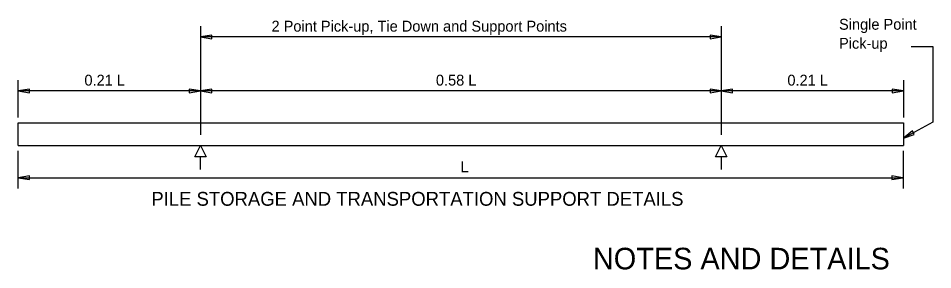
# Model space of a CAD drawing. Extents: x 0.4 to 30.4, y 0.1 to 19.4.
# Drawn here: x 17.73 to 30.43, y 0.15 to 3.64 of the extents above; entities that cross this region are included whole.
import ezdxf

# ---------------------------------------------------------------- set-up
doc = ezdxf.new("R2010")
doc.units = 0
for name, color, linetype in [('Dimension', 7, 'Continuous'), ('SheetPileConc', 7, 'Continuous'), ('TextStructures', 7, 'Continuous')]:
    doc.layers.add(name, color=color, linetype=linetype)

msp = doc.modelspace()

# ---------------------------------------------------------------- linework, layer by layer
at = {"layer": 'Dimension'}
for p, q in [((20.259, 3.529), (20.259, 2.02)), ((27.492, 3.529), (27.492, 2.02)), ((27.492, 3.381), (20.259, 3.381)), ((17.729, 2.26), (17.729, 2.779)), ((30.022, 2.779), (30.022, 2.26)), ((20.259, 2.631), (17.729, 2.631)), ((27.492, 2.631), (20.259, 2.631)), ((30.022, 2.631), (27.492, 2.631)), ((17.729, 1.277), (17.729, 1.797)), ((30.022, 1.277), (30.022, 1.797)), ((20.26, 1.541), (20.26, 1.715)), ((27.493, 1.541), (27.493, 1.715)), ((17.729, 1.426), (30.022, 1.426))]:
    msp.add_line(p, q, dxfattribs=at)
for points in [[(20.259, 3.381), (20.415, 3.355), (20.415, 3.407)], [(27.492, 3.381), (27.336, 3.407), (27.336, 3.355)], [(17.729, 2.631), (17.886, 2.605), (17.886, 2.657)], [(20.259, 2.631), (20.103, 2.657), (20.103, 2.605)], [(20.259, 2.631), (20.415, 2.605), (20.415, 2.657)], [(27.492, 2.631), (27.336, 2.657), (27.336, 2.605)], [(27.492, 2.631), (27.648, 2.605), (27.648, 2.657)], [(30.022, 2.631), (29.865, 2.657), (29.865, 2.605)], [(30.023, 1.977), (30.172, 2.028), (30.147, 2.075)], [(20.259, 1.871), (20.338, 1.715), (20.18, 1.715)], [(27.492, 1.871), (27.571, 1.715), (27.413, 1.715)], [(17.729, 1.426), (17.886, 1.399), (17.886, 1.452)], [(30.015, 1.426), (29.859, 1.452), (29.859, 1.399)]]:
    msp.add_lwpolyline(points, close=True, dxfattribs=at)
msp.add_lwpolyline([(30.131, 3.246), (30.428, 3.246), (30.428, 2.199), (30.023, 1.977)], dxfattribs=at)
at = {"layer": 'SheetPileConc'}
for p, q in [((17.729, 2.186), (30.022, 2.186)), ((17.729, 1.871), (17.729, 2.186)), ((30.022, 2.186), (30.022, 1.871)), ((17.729, 1.871), (30.022, 1.871))]:
    msp.add_line(p, q, dxfattribs=at)

# ---------------------------------------------------------------- texts
at = {"layer": 'Dimension'}
for s, p in [('Single Point', (29.127, 3.481)), ('Pick-up', (29.127, 3.217))]:
    msp.add_text(s, height=0.1512, dxfattribs=at).set_placement(p)
at = {"layer": 'TextStructures'}
for s, height, p in [('2 Point Pick-up, Tie Down and Support Points', 0.1512, (21.246, 3.455)), ('0.21 L', 0.1512, (18.648, 2.705)), ('0.58 L', 0.1512, (23.529, 2.705)), ('0.21 L', 0.1512, (28.41, 2.705)), ('L', 0.151, (23.872, 1.5)), ('PILE STORAGE AND TRANSPORTATION SUPPORT DETAILS', 0.192, (19.577, 1.036)), ('NOTES AND DETAILS', 0.3, (25.709, 0.152))]:
    msp.add_text(s, height=height, dxfattribs=at).set_placement(p)

doc.saveas('drawing.dxf')
